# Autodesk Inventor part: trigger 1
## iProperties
Created: 2006-04
Part Number: trigger 1
Document SubType Name: Modeling
Designer: Калинин
Author: Калинин
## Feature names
1. Выдавливание1 [Extrusion]
